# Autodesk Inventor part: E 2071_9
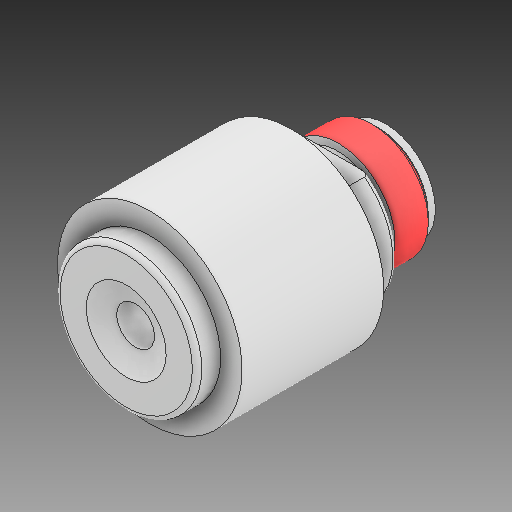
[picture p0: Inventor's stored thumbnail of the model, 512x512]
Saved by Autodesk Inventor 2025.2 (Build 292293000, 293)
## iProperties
Created: 2025-04
Part Number: E 2071_9
Material: Všeobecné
Document SubType Name: Modeling
Designer: Patrik
Density: 1 g/cm^3
Appearance: Výchozí
Mass: 43.8948 g
Surface Area: 99.449 cm^2
Volume: 43.8948 cm^3
Author: Patrik
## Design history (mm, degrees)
feature "Base1"
node "Těleso1"
